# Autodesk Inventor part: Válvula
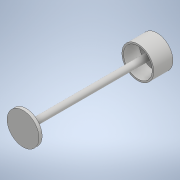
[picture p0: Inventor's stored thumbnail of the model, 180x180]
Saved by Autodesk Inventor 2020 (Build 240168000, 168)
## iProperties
Created: 2019-09
Part Number: Válvula
Material: Generic
Document SubType Name: Modeling
Designer: user
Density: 1 g/cm^3
Appearance: Default
Author: user
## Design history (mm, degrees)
sketch "Sketch1"
  geometry: C1 r 5 at (0, 0); 1 further point
  constraints: 1 centre point, 1 coincident
  dimensions: "d0" = 10 diameter of C1
extrude "Extrusion1" new body sketch "Sketch1" distance "d1" = 1; taper "d2" = 0 deg
sketch "Sketch2"
  geometry: C1 r 1 at (0, 0); 1 further point
  constraints: 1 centre point, 1 coincident
extrude "Extrusion2" join sketch "Sketch2" distance "d3" = 40; taper "d4" = 0 deg
sketch "Sketch3"
  geometry: C1 r 5 at (0, 0); 1 further point
  constraints: 1 centre point, 1 coincident
extrude "Extrusion3" join sketch "Sketch3" distance "d5" = 1; taper "d6" = 0 deg
sketch "Sketch4"
  geometry: C1 r 5 at (0, 0) reference; C2 r 5 at (0, 0); C3 r 1 at (0, 0) reference; C4 r 4.5 at (0, 0); 1 further point
  constraints: 2 centre point, 2 coincident
  dimensions: "d7" = 9 diameter of C4
extrude "Extrusion4" join sketch "Sketch4" distance "d8" = 5; taper "d9" = 0 deg
body "Solid1"
